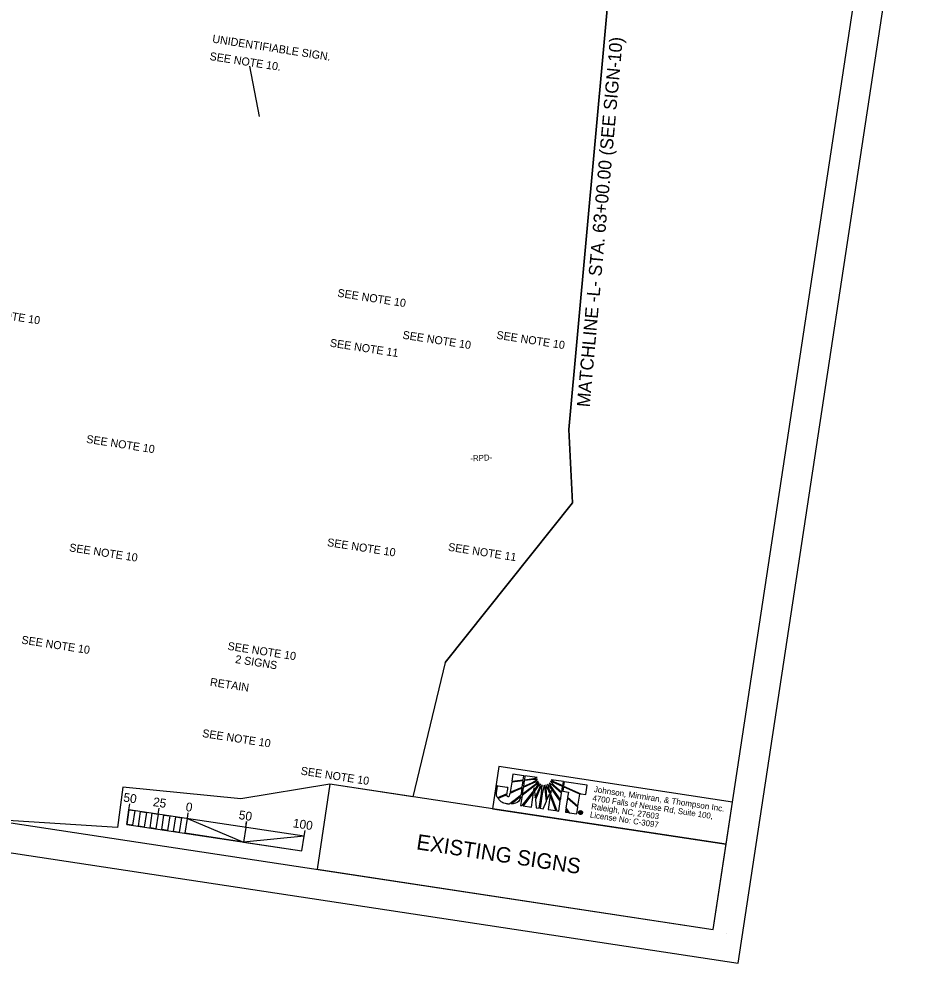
# Model space of a CAD drawing. Extents: x 1640181 to 1642275, y 841730 to 843072.
# Drawn here: x 1641287 to 1642061, y 841730 to 842529 of the extents above; entities that cross this region are included whole.
import ezdxf

# ---------------------------------------------------------------- set-up
doc = ezdxf.new("R2010")
doc.units = 0
for name, color, linetype in [('Default', 7, 'Continuous'), ('Level 14', 7, 'Continuous'), ('Level 2', 7, 'Continuous'), ('Level 22', 7, 'Continuous'), ('Level 23', 7, 'Continuous'), ('Level 25', 7, 'Continuous'), ('Level 3', 7, 'Continuous'), ('Level 38', 7, 'Continuous'), ('Level 5', 7, 'Continuous'), ('Level 6', 7, 'Continuous')]:
    doc.layers.add(name, color=color, linetype=linetype)

msp = doc.modelspace()

# ---------------------------------------------------------------- linework, layer by layer
at = {"layer": 'Default'}
for p, q in [((1641705.07, 841890.31), (1641704.14, 841884.17)), ((1641714.32, 841888.92), (1641705.07, 841890.31)), ((1641713.78, 841885.34), (1641714.32, 841888.92)), ((1641715.29, 841888.82), (1641714.79, 841885.5)), ((1641714.79, 841885.5), (1641722.88, 841886.47)), ((1641725.71, 841887.25), (1641715.29, 841888.82)), ((1641722.88, 841886.47), (1641725.71, 841887.25)), ((1641704.04, 841883.47), (1641702.73, 841874.84)), ((1641702.73, 841874.84), (1641712.87, 841879.31)), ((1641713.68, 841884.67), (1641704.04, 841883.47)), ((1641704.14, 841884.17), (1641713.78, 841885.34)), ((1641724.55, 841881.31), (1641712.79, 841872.21)), ((1641712.87, 841879.31), (1641713.68, 841884.67)), ((1641712.94, 841873.19), (1641724.23, 841881.88)), ((1641713.81, 841878.96), (1641712.94, 841873.19)), ((1641722.6, 841882.86), (1641713.81, 841878.96)), ((1641714.68, 841884.78), (1641713.93, 841879.77)), ((1641713.93, 841879.77), (1641721.54, 841883.12)), ((1641722.77, 841885.75), (1641714.68, 841884.78)), ((1641721.54, 841883.12), (1641725.85, 841885.66)), ((1641726.39, 841884.11), (1641722.6, 841882.86)), ((1641722.67, 841876.11), (1641723.04, 841878.56)), ((1641725.85, 841885.66), (1641722.77, 841885.75)), ((1641723.04, 841878.56), (1641723.25, 841876.81)), ((1641723.25, 841876.81), (1641725.72, 841880.04)), ((1641726.31, 841879.73), (1641723.37, 841875.9)), ((1641724.02, 841870.11), (1641727.81, 841878.99)), ((1641728.25, 841878.4), (1641724.13, 841868.78)), ((1641724.23, 841881.88), (1641726.39, 841884.11)), ((1641727.3, 841882.84), (1641724.55, 841881.31)), ((1641725.72, 841880.04), (1641727.3, 841882.84)), ((1641728.5, 841881.81), (1641726.31, 841879.73)), ((1641727.81, 841878.99), (1641728.5, 841881.81)), ((1641729.96, 841881.17), (1641728.25, 841878.4)), ((1641729.26, 841873.81), (1641729.96, 841881.17)), ((1641731.49, 841880.94), (1641729.92, 841873.71)), ((1641732.27, 841877.79), (1641731.49, 841880.94)), ((1641733.04, 841881.13), (1641732.89, 841878.12)), ((1641732.89, 841878.12), (1641733.88, 841868.41)), ((1641734.47, 841878.5), (1641733.04, 841881.13)), ((1641734.47, 841881.75), (1641735.16, 841878.62)), ((1641736.65, 841879.49), (1641734.47, 841881.75)), ((1641736.21, 841873.8), (1641734.47, 841878.5)), ((1641735.16, 841878.62), (1641736.59, 841874.64)), ((1641735.73, 841882.7), (1641737.13, 841879.88)), ((1641739.03, 841880.38), (1641735.73, 841882.7)), ((1641745.19, 841867.23), (1641736.65, 841879.49)), ((1641736.75, 841884.02), (1641740.15, 841880.26)), ((1641739.55, 841883.22), (1641736.75, 841884.02)), ((1641737.13, 841879.88), (1641745.33, 841868.2)), ((1641747.76, 841883.87), (1641737.5, 841885.47)), ((1641737.5, 841885.47), (1641739.92, 841883.85)), ((1641746.23, 841874.12), (1641739.03, 841880.38)), ((1641747.15, 841879.84), (1641739.55, 841883.22)), ((1641739.92, 841883.85), (1641747.26, 841880.54)), ((1641740.15, 841880.26), (1641746.35, 841874.95)), ((1641746.35, 841874.95), (1641747.15, 841879.84)), ((1641747.26, 841880.54), (1641747.76, 841883.87)), ((1641747.84, 841879.52), (1641747.28, 841875.79)), ((1641747.85, 841879.58), (1641747.84, 841879.52)), ((1641761.57, 841873.32), (1641747.85, 841879.58)), ((1641747.95, 841880.24), (1641747.93, 841880.13)), ((1641747.93, 841880.13), (1641762.6, 841873.53)), ((1641748.49, 841883.81), (1641747.95, 841880.24)), ((1641767.95, 841880.88), (1641748.49, 841883.81)), ((1641766.74, 841872.9), (1641767.95, 841880.88)), ((1641712.79, 841872.21), (1641711.52, 841863.81)), ((1641713.05, 841863.58), (1641722.67, 841876.11)), ((1641722.47, 841874.78), (1641713.77, 841863.47)), ((1641720.67, 841862.43), (1641722.47, 841874.78)), ((1641723.37, 841875.9), (1641724.02, 841870.11)), ((1641727.4, 841861.46), (1641729.26, 841873.81)), ((1641729.92, 841873.71), (1641728.06, 841861.36)), ((1641733.39, 841867.23), (1641732.27, 841877.79)), ((1641733.88, 841868.41), (1641736.21, 841873.8)), ((1641736.73, 841872.37), (1641734.92, 841860.33)), ((1641736.59, 841874.64), (1641737.34, 841876.4)), ((1641741.54, 841859.33), (1641736.73, 841872.37)), ((1641737.34, 841876.4), (1641736.93, 841873.7)), ((1641736.93, 841873.7), (1641742.3, 841859.17)), ((1641745.33, 841868.2), (1641746.23, 841874.12)), ((1641747.28, 841875.79), (1641752.03, 841875.08)), ((1641752.03, 841875.08), (1641751.36, 841870.63)), ((1641751.36, 841870.63), (1641760.03, 841863.1)), ((1641760.03, 841863.1), (1641761.57, 841873.32)), ((1641762.6, 841873.53), (1641766.74, 841872.9)), ((1641711.52, 841863.81), (1641713.05, 841863.58)), ((1641713.77, 841863.47), (1641720.67, 841862.43)), ((1641724.13, 841868.78), (1641724.86, 841861.85)), ((1641730.62, 841860.98), (1641733.39, 841867.23)), ((1641743.94, 841858.92), (1641745.19, 841867.23)), ((1641751.24, 841869.87), (1641749.99, 841861.59)), ((1641759.92, 841862.39), (1641751.24, 841869.87)), ((1641759.06, 841856.64), (1641759.92, 841862.39)), ((1641724.86, 841861.85), (1641727.4, 841861.46)), ((1641728.06, 841861.36), (1641730.62, 841860.98)), ((1641734.92, 841860.33), (1641741.54, 841859.33)), ((1641742.3, 841859.17), (1641743.94, 841858.92)), ((1641749.86, 841860.69), (1641749.47, 841858.09)), ((1641749.47, 841858.09), (1641751.86, 841857.73)), ((1641751.86, 841857.73), (1641749.86, 841860.69)), ((1641749.99, 841861.59), (1641752.78, 841857.59)), ((1641752.78, 841857.59), (1641759.06, 841856.64)), ((1641761.63, 841857.15), (1641761.84, 841858.56)), ((1641761.95, 841857.1), (1641761.63, 841857.15)), ((1641761.84, 841858.56), (1641762.42, 841858.48)), ((1641762.03, 841857.65), (1641761.95, 841857.1)), ((1641762.29, 841857.62), (1641762.03, 841857.65)), ((1641762.12, 841858.25), (1641762.07, 841857.91)), ((1641762.07, 841857.91), (1641762.33, 841857.87)), ((1641762.12, 841856.51), (1641762.08, 841856.2)), ((1641762.08, 841856.2), (1641762.12, 841856.51)), ((1641762.09, 841856.2), (1641762.08, 841856.2)), ((1641762.38, 841858.21), (1641762.12, 841858.25)), ((1641762.12, 841856.51), (1641762.14, 841856.51)), ((1641762.33, 841857.87), (1641762.29, 841857.62)), ((1641762.29, 841857.62), (1641762.33, 841857.87)), ((1641762.3, 841857.61), (1641762.29, 841857.62)), ((1641762.33, 841857.87), (1641762.34, 841857.87)), ((1641762.42, 841858.48), (1641762.38, 841858.21)), ((1641762.38, 841858.21), (1641762.42, 841858.48)), ((1641762.42, 841858.2), (1641762.38, 841858.21)), ((1641762.42, 841858.48), (1641762.51, 841858.46)), ((1641762.55, 841859.31), (1641762.5, 841859.02)), ((1641762.5, 841859.02), (1641762.55, 841859.31))]:
    msp.add_line(p, q, dxfattribs=at)
msp.add_lwpolyline([(1641687.8, 841860.9), (1641885.57, 841830.89), (1641890.99, 841866.58), (1641693.21, 841896.59)], close=True, dxfattribs=at)
for points in [[(1641704.14, 841884.17), (1641713.78, 841885.34), (1641714.32, 841888.92), (1641705.07, 841890.31), (1641704.14, 841884.17)], [(1641722.88, 841886.47), (1641725.71, 841887.25), (1641715.29, 841888.82), (1641714.79, 841885.5), (1641722.88, 841886.47)], [(1641702.73, 841874.84), (1641712.87, 841879.31), (1641713.68, 841884.67), (1641704.04, 841883.47), (1641702.73, 841874.84)], [(1641727.3, 841882.84), (1641724.55, 841881.31), (1641712.79, 841872.21), (1641711.52, 841863.81), (1641713.05, 841863.58), (1641722.67, 841876.11), (1641723.04, 841878.56), (1641723.25, 841876.81), (1641725.72, 841880.04), (1641727.3, 841882.84)], [(1641713.81, 841878.96), (1641712.94, 841873.19), (1641724.23, 841881.88), (1641726.39, 841884.11), (1641722.6, 841882.86), (1641713.81, 841878.96)], [(1641714.68, 841884.78), (1641713.93, 841879.77), (1641721.54, 841883.12), (1641725.85, 841885.66), (1641722.77, 841885.75), (1641714.68, 841884.78)], [(1641728.5, 841881.81), (1641726.31, 841879.73), (1641723.37, 841875.9), (1641724.02, 841870.11), (1641727.81, 841878.99), (1641728.5, 841881.81)], [(1641728.25, 841878.4), (1641724.13, 841868.78), (1641724.86, 841861.85), (1641727.4, 841861.46), (1641729.26, 841873.81), (1641729.96, 841881.17), (1641728.25, 841878.4)], [(1641731.49, 841880.94), (1641729.92, 841873.71), (1641728.06, 841861.36), (1641730.62, 841860.98), (1641733.39, 841867.23), (1641732.27, 841877.79), (1641731.49, 841880.94)], [(1641733.04, 841881.13), (1641732.89, 841878.12), (1641733.88, 841868.41), (1641736.21, 841873.8), (1641734.47, 841878.5), (1641733.04, 841881.13)], [(1641734.47, 841881.75), (1641735.16, 841878.62), (1641736.59, 841874.64), (1641737.34, 841876.4), (1641736.93, 841873.7), (1641742.3, 841859.17), (1641743.94, 841858.92), (1641745.19, 841867.23), (1641736.65, 841879.49), (1641734.47, 841881.75)], [(1641735.73, 841882.7), (1641737.13, 841879.88), (1641745.33, 841868.2), (1641746.23, 841874.12), (1641739.03, 841880.38), (1641735.73, 841882.7)], [(1641736.75, 841884.02), (1641740.15, 841880.26), (1641746.35, 841874.95), (1641747.15, 841879.84), (1641739.55, 841883.22), (1641736.75, 841884.02)], [(1641739.92, 841883.85), (1641747.26, 841880.54), (1641747.76, 841883.87), (1641737.5, 841885.47), (1641739.92, 841883.85)], [(1641747.85, 841879.58), (1641747.84, 841879.52), (1641747.28, 841875.79), (1641752.03, 841875.08), (1641751.36, 841870.63), (1641760.03, 841863.1), (1641761.57, 841873.32), (1641747.85, 841879.58)], [(1641767.95, 841880.88), (1641748.49, 841883.81), (1641747.95, 841880.24), (1641747.93, 841880.13), (1641762.6, 841873.53), (1641766.74, 841872.9), (1641767.95, 841880.88)], [(1641713.77, 841863.47), (1641720.67, 841862.43), (1641722.47, 841874.78), (1641713.77, 841863.47)], [(1641734.92, 841860.33), (1641741.54, 841859.33), (1641736.73, 841872.37), (1641734.92, 841860.33)], [(1641751.24, 841869.87), (1641749.99, 841861.59), (1641752.78, 841857.59), (1641759.06, 841856.64), (1641759.92, 841862.39), (1641751.24, 841869.87), (1641751.24, 841869.87)], [(1641749.47, 841858.09), (1641749.47, 841858.09), (1641751.86, 841857.73), (1641749.86, 841860.69), (1641749.47, 841858.09)], [(1641762.87, 841857.3), (1641762.86, 841857.23), (1641762.87, 841857.17), (1641762.86, 841857.12), (1641762.87, 841856.96), (1641762.58, 841857.01)]]:
    msp.add_lwpolyline(points, dxfattribs=at)
for points, degree in [([(1641700.67, 841879.21), (1641700.67, 841879.21), (1641692.11, 841880.5), (1641692.11, 841880.5), (1641692.11, 841880.5), (1641691.3, 841875.14), (1641691.3, 841875.14), (1641691.3, 841875.14), (1641691.21, 841874.58), (1641691.21, 841874.58), (1641690.96, 841872.9), (1641691.31, 841871.48), (1641692.12, 841870.22), (1641692.12, 841870.22), (1641699.8, 841873.44), (1641699.82, 841873.54), (1641699.82, 841873.54), (1641700.67, 841879.21), (1641700.67, 841879.21)], 3), ([(1641700.84, 841871.3), (1641700.29, 841871.38), (1641699.86, 841871.76), (1641699.82, 841872.81), (1641699.82, 841872.81), (1641692.55, 841869.7), (1641692.55, 841869.7), (1641694.28, 841867.24), (1641697.35, 841865.46), (1641700.12, 841865.05), (1641700.84, 841864.94), (1641701.39, 841864.92), (1641702.18, 841864.95), (1641702.18, 841864.95), (1641711.82, 841872.31), (1641711.82, 841872.31), (1641711.82, 841872.31), (1641712.76, 841878.54), (1641712.76, 841878.54), (1641712.76, 841878.54), (1641702.62, 841874.06), (1641702.62, 841874.06), (1641702.26, 841871.72), (1641701.6, 841871.18), (1641700.84, 841871.3)], 3), ([(1641700.84, 841871.3), (1641700.29, 841871.38), (1641699.86, 841871.76), (1641699.82, 841872.81), (1641699.82, 841872.81), (1641692.55, 841869.7), (1641692.55, 841869.7), (1641694.28, 841867.24), (1641697.35, 841865.46), (1641700.12, 841865.05), (1641700.84, 841864.94), (1641701.39, 841864.92), (1641702.18, 841864.95), (1641702.18, 841864.95), (1641711.82, 841872.31), (1641711.82, 841872.31), (1641711.82, 841872.31), (1641712.76, 841878.54), (1641712.76, 841878.54), (1641712.76, 841878.54), (1641702.62, 841874.06), (1641702.62, 841874.06), (1641702.26, 841871.72), (1641701.6, 841871.18), (1641700.84, 841871.3)], 3), ([(1641711.67, 841871.33), (1641711.67, 841871.33), (1641703.34, 841864.98), (1641703.34, 841864.98), (1641707, 841865.32), (1641710.87, 841867.13), (1641711.67, 841871.33)], 3), ([(1641762.08, 841856.2), (1641761.65, 841856.26), (1641761.3, 841856.48), (1641761.04, 841856.83), (1641760.78, 841857.17), (1641760.68, 841857.57), (1641760.74, 841858.01), (1641760.81, 841858.44), (1641761.02, 841858.79), (1641761.37, 841859.03), (1641761.72, 841859.28), (1641762.11, 841859.38), (1641762.55, 841859.31)], 3), ([(1641762.5, 841859.02), (1641762.15, 841859.07), (1641761.84, 841859), (1641761.56, 841858.8), (1641761.28, 841858.6), (1641761.1, 841858.31), (1641761.05, 841857.96), (1641761, 841857.61), (1641761.08, 841857.28), (1641761.29, 841857), (1641761.5, 841856.72), (1641761.78, 841856.56), (1641762.12, 841856.51)], 3), ([(1641763.9, 841857.53), (1641763.83, 841857.09), (1641763.62, 841856.74), (1641763.28, 841856.48), (1641762.92, 841856.23), (1641762.53, 841856.13), (1641762.09, 841856.2)], 3), ([(1641762.14, 841856.51), (1641762.48, 841856.46), (1641762.8, 841856.53), (1641763.08, 841856.73), (1641763.36, 841856.94), (1641763.53, 841857.23), (1641763.59, 841857.58), (1641763.64, 841857.93), (1641763.56, 841858.25), (1641763.35, 841858.53), (1641763.14, 841858.8), (1641762.86, 841858.96), (1641762.5, 841859.02)], 3), ([(1641762.54, 841857.53), (1641762.5, 841857.56), (1641762.43, 841857.59), (1641762.3, 841857.61)], 2), ([(1641762.34, 841857.87), (1641762.55, 841857.84), (1641762.66, 841857.89), (1641762.68, 841858), (1641762.69, 841858.11), (1641762.61, 841858.17), (1641762.42, 841858.2)], 3), ([(1641762.51, 841858.46), (1641762.87, 841858.41), (1641763.03, 841858.24), (1641762.99, 841857.96), (1641762.97, 841857.83), (1641762.9, 841857.73), (1641762.77, 841857.67)], 3), ([(1641762.58, 841857.01), (1641762.55, 841857.09), (1641762.54, 841857.17), (1641762.55, 841857.27), (1641762.57, 841857.4), (1641762.57, 841857.48), (1641762.54, 841857.53)], 3), ([(1641762.55, 841859.31), (1641762.98, 841859.25), (1641763.33, 841859.04), (1641763.6, 841858.69), (1641763.86, 841858.37), (1641763.96, 841857.97), (1641763.9, 841857.53)], 3), ([(1641762.77, 841857.67), (1641762.85, 841857.61), (1641762.89, 841857.49), (1641762.87, 841857.3)], 2)]:
    msp.add_open_spline(points, degree=degree, dxfattribs=at)
at = {"layer": 'Level 14'}
msp.add_lwpolyline([(1641647.83, 841984.74), (1641755.46, 842119.79), (1641752.38, 842181.83), (1641796.56, 842667.29)], dxfattribs=at)
at = {"layer": 'Level 2'}
msp.add_lwpolyline([(1640226.71, 841983.66), (1641895.61, 841730.39), (1642060.65, 842817.94), (1640391.76, 843071.21)], close=True, dxfattribs=at)
msp.add_lwpolyline([(1640226.71, 841983.66), (1641895.61, 841730.39), (1642060.65, 842817.94), (1640391.76, 843071.21)], close=True, dxfattribs=at)
at = {"layer": 'Level 23'}
for p, q in [((1641380.17, 841860.12), (1641380.92, 841865.05)), ((1641380.17, 841860.12), (1641378.3, 841847.76)), ((1641528.47, 841837.63), (1641380.17, 841860.12)), ((1641404.89, 841856.36), (1641405.64, 841861.32)), ((1641414.77, 841854.87), (1641412.9, 841842.52)), ((1641429.6, 841852.61), (1641430.35, 841857.56)), ((1641378.3, 841847.76), (1641526.6, 841825.26)), ((1641479.04, 841845.13), (1641479.79, 841850.06)), ((1641479.04, 841845.13), (1641477.16, 841832.77)), ((1641528.47, 841837.63), (1641529.22, 841842.57)), ((1641526.6, 841825.26), (1641528.47, 841837.63))]:
    msp.add_line(p, q, dxfattribs=at)
for points in [[(1641539.34, 841809.74), (1641874.64, 841758.86), (1641885.57, 841830.89), (1641550.27, 841881.77)], [(1641380.17, 841860.12), (1641385.11, 841859.37), (1641383.24, 841847.01), (1641378.3, 841847.76)], [(1641390.06, 841858.62), (1641395, 841857.86), (1641393.12, 841845.5), (1641388.19, 841846.25)], [(1641399.94, 841857.11), (1641404.89, 841856.36), (1641403.01, 841844.01), (1641398.07, 841844.76)], [(1641409.83, 841855.61), (1641414.77, 841854.87), (1641412.9, 841842.52), (1641407.96, 841843.27)], [(1641419.72, 841854.12), (1641424.66, 841853.37), (1641422.79, 841841), (1641417.84, 841841.77)], [(1641429.6, 841852.61), (1641477.16, 841832.77), (1641427.73, 841840.25)], [(1641528.47, 841837.63), (1641477.16, 841832.77), (1641526.6, 841825.26)]]:
    msp.add_lwpolyline(points, close=True, dxfattribs=at)
at = {"layer": 'Level 25'}
for p, q in [((1641380.18, 841860.13), (1641380.93, 841865.06)), ((1641404.9, 841856.37), (1641405.65, 841861.32)), ((1641479.05, 841845.14), (1641479.8, 841850.07)), ((1641528.49, 841837.63), (1641529.24, 841842.58))]:
    msp.add_line(p, q, dxfattribs=at)
at = {"layer": 'Level 3'}
for p, q in [((1641885.4, 841755.65), (1641885.4, 841755.65)), ((1641895.59, 841730.37), (1641895.59, 841730.37))]:
    msp.add_line(p, q, dxfattribs=at)
msp.add_lwpolyline([(1642032.34, 842798.03), (1640550.03, 843022.98), (1640392.33, 841983.81), (1641874.64, 841758.86)], close=True, dxfattribs=at)
at = {"layer": 'Level 38'}
msp.add_line((1641490.57, 842446.48), (1641482.45, 842489.1), dxfattribs=at)
at = {"layer": 'Level 6'}
msp.add_lwpolyline([(1640495.4, 842368.43), (1640578.69, 842512.77), (1640617.73, 842617.59), (1640629.05, 842742.44), (1640614.97, 842767.52), (1640908.06, 842958.77), (1641847.47, 842826.08), (1641796.56, 842667.29), (1641752.38, 842181.83), (1641755.46, 842119.79), (1641647.87, 841984.79), (1641620.53, 841871.11), (1641550.27, 841881.77), (1641474.89, 841869.36), (1641375.09, 841879.22), (1641370.37, 841845.01), (1641259.98, 841852.14), (1640964.13, 841969.33), (1640641.82, 842236.89)], close=True, dxfattribs=at)

# ---------------------------------------------------------------- texts
at = {"layer": 'Default'}
for s, height, rotation, p in [('UNIDENTIFIABLE SIGN.', 6.7709, 351.20994, (1641450.38, 842509.14)), ('SEE NOTE 10.', 6.7709, 351.20994, (1641448.11, 842494.41)), ('SEE NOTE 10', 6.7709, 351.20994, (1641556.28, 842294.18)), ('SEE NOTE 10', 6.7709, 351.20994, (1641246.8, 842279.53)), ('SEE NOTE 10', 6.7709, 351.20994, (1641611.39, 842258.64)), ('SEE NOTE 10', 6.7709, 351.20994, (1641690.8, 842258.62)), ('SEE NOTE 11', 6.7709, 351.20994, (1641549.88, 842251.94)), ('SEE NOTE 10', 6.7709, 351.20994, (1641343.76, 842170.58)), ('SEE NOTE 10', 6.7709, 351.20994, (1641547.54, 842083.2)), ('SEE NOTE 11', 6.7709, 351.20994, (1641649.87, 842079.27)), ('SEE NOTE 10', 6.7709, 351.20994, (1641329.31, 842078.83)), ('SEE NOTE 10', 6.7709, 351.20994, (1641288.88, 842000.73)), ('SEE NOTE 10', 6.7709, 351.20994, (1641463.32, 841995.48)), ('2 SIGNS', 6.771, 351.20994, (1641469.77, 841984.3)), ('RETAIN', 6.771, 351.20994, (1641448.42, 841965.04)), ('SEE NOTE 10', 6.7709, 351.20994, (1641441.84, 841921.68)), ('SEE NOTE 10', 6.7709, 351.20994, (1641525.21, 841889.93)), ('Johnson, Mirmiran, & Thompson Inc.', 5.1112, 351.37069, (1641773.27, 841875.09)), ('4700 Falls of Neuse Rd, Suite 100, ', 4.9652, 351.37069, (1641772.15, 841867.67)), ('Raleigh, NC, 27603', 4.9652, 351.37069, (1641771.08, 841860.66)), ('License No: C-3097', 4.9652, 351.37069, (1641770.02, 841853.64)), ('EXISTING SIGNS', 13, 351.37069, (1641622.87, 841826.73))]:
    msp.add_text(s, height=height, rotation=rotation, dxfattribs=at).set_placement(p)
at = {"layer": 'Level 22'}
msp.add_text('MATCHLINE -L- STA. 63+00.00 (SEE SIGN-10)', height=11, rotation=84.86416, dxfattribs=at).set_placement((1641770.04, 842200.32))
at = {"layer": 'Level 23'}
for s, p in [('50', (1641375.09, 841867.1)), ('25', (1641400.14, 841863.3)), ('0', (1641427.81, 841859.11)), ('50', (1641472.73, 841852.29)), ('100', (1641518.55, 841845.34))]:
    msp.add_text(s, height=7.5, rotation=351.37546, dxfattribs=at).set_placement(p)
at = {"layer": 'Level 5'}
msp.add_text('-RPD-', height=5, rotation=2.83604, dxfattribs=at).set_placement((1641669.17, 842154.82))

doc.saveas('drawing.dxf')
